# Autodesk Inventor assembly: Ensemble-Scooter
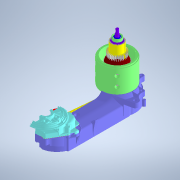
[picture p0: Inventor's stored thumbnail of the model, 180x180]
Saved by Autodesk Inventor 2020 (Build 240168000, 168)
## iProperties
Created: 2020-09
Part Number: Ensemble-Scooter
Document SubType Name: Assembly
Designer: Bruno
Author: Bruno
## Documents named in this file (5)
- D:\Téléchargements-2016-17\scoot_elec\Ensemble-Scooter.iam
- D:\Téléchargements-2016-17\scoot_elec\Transmission scoot elec.iam
- D:\Téléchargements-2016-17\scoot_elec\Ensemble-arbre-moteur.iam
- D:\Téléchargements-2016-17\scoot_elec\Ensemble-arbre-intermédiaire.iam
- D:\Téléchargements-2016-17\scoot_elec\pièces à assembler\Courroie crantée.ipt
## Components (4 placed, 4 different names)
1. Transmission scoot elec:1 [sub-assembly] — Logement:1, Logement:2
2. Ensemble-arbre-moteur:1 [sub-assembly] — Logement:1, Placage:1
3. Ensemble-arbre-intermédiaire:1 [sub-assembly] — Logement:2, Placage:2, Affleurement:1
4. Courroie crantée:1 — Placage:1, Placage:2, Affleurement:1
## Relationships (5: Insert 2, Mate 2, Flush 1)
- Logement:1 [Insert]: Transmission scoot elec:1 ↔ Ensemble-arbre-moteur:1
- Logement:2 [Insert]: Transmission scoot elec:1 ↔ Ensemble-arbre-intermédiaire:1
- Placage:1 [Mate]: Ensemble-arbre-moteur:1 ↔ Courroie crantée:1
- Placage:2 [Mate]: Ensemble-arbre-intermédiaire:1 ↔ Courroie crantée:1
- Affleurement:1 [Flush]: Ensemble-arbre-intermédiaire:1 ↔ Courroie crantée:1
